Omron Sysmac Studio project CIF105与4543V通讯 (Sysmac Studio 1.25.1.0, StandardProject)

# Controller new_Controller_0: NX1P2-9024DT version 1.16
Task PrimaryTask (priority 4, period or condition 2000): Program0

TYPE TypeBD4543 : STRUCT
    PV : ARRAY[0..15] OF INT;  (* 实际温度、报警状态、故障状态（只读） *)
    RUNF : INT;  (* 通道故障（只读） *)
    ALF1 : INT;  (* 报警1状态（只读） *)
    ALF2 : INT;  (* 报警2状态（只读） *)
    ONB : INT;  (* 启动温控（可读可写） *)
    ATUB : INT;  (* 自整定（可读可写） *)
    SV : ARRAY[0..15] OF INT;  (* 设定温度（可读可写） *)
    Pb : ARRAY[0..15] OF INT;  (* 温度偏置（可读可写） *)
    running : INT;  (* 通信计数 *)
    error : INT;  (* 通信故障计数 *)
    tmp : ARRAY[0..34] OF INT;  (* 中间数据（只读） *)
END_STRUCT END_TYPE

VAR_GLOBAL
    P1 : _sDEVICE_PORT;
    P0 : _sDEVICE_PORT;
END_VAR
VAR_GLOBAL CONSTANT
    Port1 : _sNXUNIT_ID := (NodeAdr := 65535, IPAdr := [5(16#FF)], UnitNo := 1, Path := [16#1, 16#0, 16#2, 16#0, 16#1, 59(16#0)], PathLength := 6);
END_VAR
VAR_GLOBAL
    BD4543 : ARRAY[0..9] OF TypeBD4543;  (* published *)
END_VAR
VAR_GLOBAL CONSTANT
    Port0 : _sOPTBOARD_ID := (SlotNo := 1, IPAdr := [5(16#0)]);
END_VAR

PROGRAM Program0
VAR
    abc : BOOL;
    CMM : BD_Modbus;
END_VAR
VAR_EXTERNAL
    P1 : _sDEVICE_PORT;
END_VAR
VAR_EXTERNAL CONSTANT
    Port1 : _sNXUNIT_ID;
END_VAR
VAR_EXTERNAL
    P0 : _sDEVICE_PORT;
END_VAR
VAR_EXTERNAL CONSTANT
    Port0 : _sOPTBOARD_ID;
END_VAR

(* Section Section0: ladder, written here as Structured Text *)

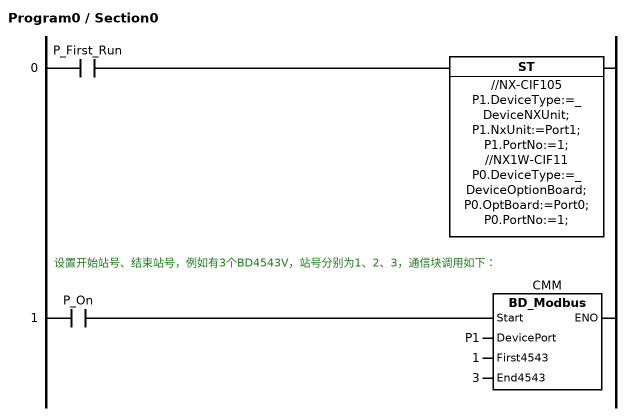
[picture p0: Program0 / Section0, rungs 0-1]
(* Rung 0 *)
IF P_First_Run THEN
    //NX-CIF105
    P1.DeviceType:=_DeviceNXUnit;
    P1.NxUnit:=Port1;
    P1.PortNo:=1;
    
    //NX1W-CIF11
    P0.DeviceType:=_DeviceOptionBoard;
    P0.OptBoard:=Port0;
    P0.PortNo:=1;
END_IF;
(* Rung 1: 设置开始站号、结束站号，例如有3个BD4543V，站号分别为1、2、3，通信块调用如下： *)
CMM(Start := P_On, DevicePort := P1, First4543 := 1, End4543 := 3);
END_PROGRAM

FUNCTION_BLOCK BD_Modbus
VAR
    StartRead : BOOL;
    CurrentSlave : UINT;
    ReadCmd : _sSERIAL_MODBUSRTU_READ;
    Option : _sSERIAL_MODBUSRTU_OPTION;
    Busy1 : BOOL;
    Done1 : BOOL;
    Error1 : BOOL;
    MB_READ_REG : NX_ModbusRtuRead;
    StartWrite : BOOL;
    MB_WRITE_REG : NX_ModbusRtuWrite;
    Done2 : BOOL;
    Busy2 : BOOL;
    Error2 : BOOL;
    WriteCmd : _sSERIAL_MODBUSRTU_WRITE;
    State : INT;
    Index : INT;
    i : INT;
    j : INT;
    k : INT;
    timer1 : TIME;
    OverTime : BOOL;
    Time1 : TON;
    BUSY : BOOL := False;
    errorID : WORD;
    erorIDEX : DWORD;
    ReadSize : UINT;
    recvbuff : ARRAY[0..120] OF WORD;
    senbuff : ARRAY[0..120] OF WORD;
END_VAR
VAR_INPUT
    Start : BOOL;
    DevicePort : _sDEVICE_PORT;
    First4543 : UINT;  (* 首个4543站号 *)
    End4543 : UINT;  (* 末个4543站号 *)
END_VAR
VAR_EXTERNAL
    BD4543 : ARRAY[0..9] OF TypeBD4543;
END_VAR
(* ladder, written here as Structured Text *)

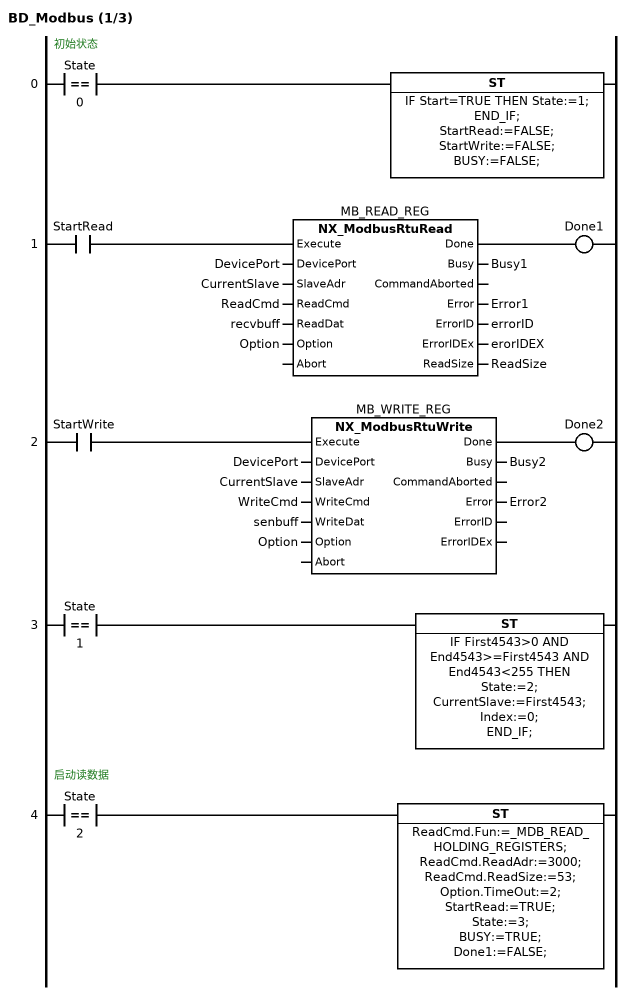
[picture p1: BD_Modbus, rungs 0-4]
(* Rung 0: 初始状态 *)
IF State = 0 THEN
    IF Start=TRUE THEN State:=1; 
    END_IF;
    StartRead:=FALSE;
    StartWrite:=FALSE;
    BUSY:=FALSE;
END_IF;
(* Rung 1 *)
MB_READ_REG(Execute := StartRead, DevicePort := DevicePort, SlaveAdr := CurrentSlave, ReadCmd := ReadCmd, ReadDat := recvbuff, Option := Option, Busy => Busy1, Error => Error1, ErrorID => errorID, ErrorIDEx => erorIDEX, ReadSize => ReadSize);
Done1 := MB_READ_REG.Done;
(* Rung 2 *)
MB_WRITE_REG(Execute := StartWrite, DevicePort := DevicePort, SlaveAdr := CurrentSlave, WriteCmd := WriteCmd, WriteDat := senbuff, Option := Option, Busy => Busy2, Error => Error2);
Done2 := MB_WRITE_REG.Done;
(* Rung 3 *)
IF State = 1 THEN
    IF First4543>0 AND End4543>=First4543 AND End4543<255 THEN
    	State:=2;
    	CurrentSlave:=First4543;
    	Index:=0;
    END_IF;
END_IF;
(* Rung 4: 启动读数据 *)
IF State = 2 THEN
    ReadCmd.Fun:=_MDB_READ_HOLDING_REGISTERS;
    ReadCmd.ReadAdr:=3000;
    ReadCmd.ReadSize:=53;
    Option.TimeOut:=2;
    StartRead:=TRUE;
    State:=3;
    BUSY:=TRUE;
    Done1:=FALSE;
END_IF;

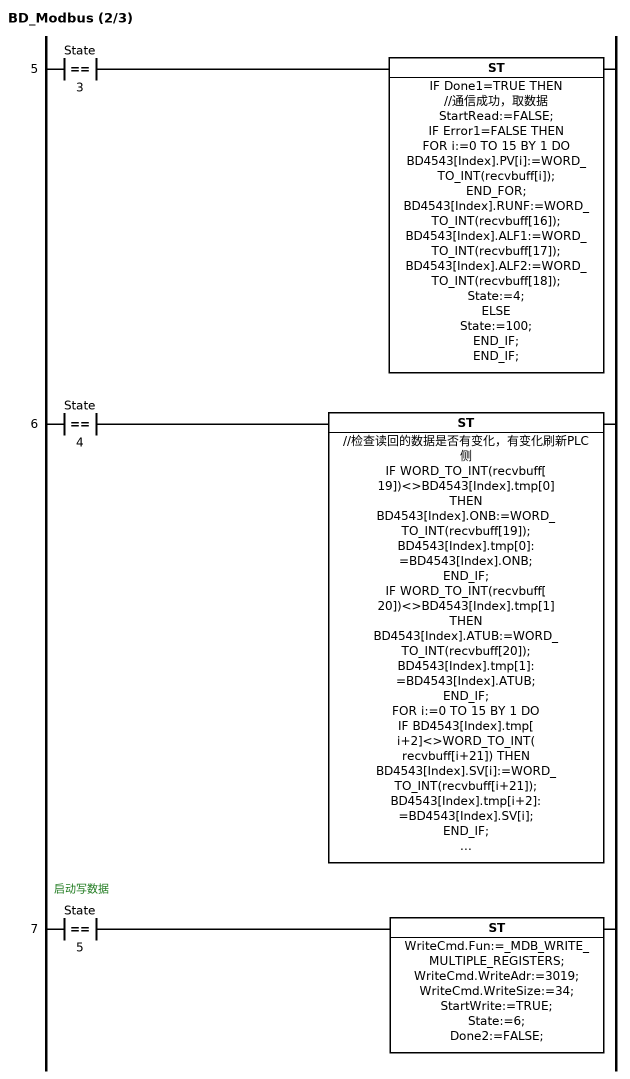
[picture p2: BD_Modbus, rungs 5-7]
(* Rung 5 *)
IF State = 3 THEN
    IF Done1=TRUE THEN			//通信成功，取数据
    	StartRead:=FALSE;
    	IF Error1=FALSE THEN	
    		FOR i:=0 TO 15 BY 1 DO
    			BD4543[Index].PV[i]:=WORD_TO_INT(recvbuff[i]);
    		END_FOR;		
    		BD4543[Index].RUNF:=WORD_TO_INT(recvbuff[16]);
    		BD4543[Index].ALF1:=WORD_TO_INT(recvbuff[17]);
    		BD4543[Index].ALF2:=WORD_TO_INT(recvbuff[18]);
    		State:=4;
    	ELSE
    		State:=100;
    	END_IF;
    END_IF;
END_IF;
(* Rung 6 *)
IF State = 4 THEN
    //检查读回的数据是否有变化，有变化刷新PLC侧
    IF WORD_TO_INT(recvbuff[19])<>BD4543[Index].tmp[0] THEN
    	BD4543[Index].ONB:=WORD_TO_INT(recvbuff[19]);
    	BD4543[Index].tmp[0]:=BD4543[Index].ONB;
    END_IF;
    IF WORD_TO_INT(recvbuff[20])<>BD4543[Index].tmp[1] THEN
    	BD4543[Index].ATUB:=WORD_TO_INT(recvbuff[20]);
    	BD4543[Index].tmp[1]:=BD4543[Index].ATUB;
    END_IF;
    FOR i:=0 TO 15 BY 1 DO
    	IF BD4543[Index].tmp[i+2]<>WORD_TO_INT(recvbuff[i+21]) THEN
    		BD4543[Index].SV[i]:=WORD_TO_INT(recvbuff[i+21]);
    		BD4543[Index].tmp[i+2]:=BD4543[Index].SV[i];
    	END_IF;
    	IF BD4543[Index].tmp[i+18]<>WORD_TO_INT(recvbuff[i+37]) THEN
    		BD4543[Index].Pb[i]:=WORD_TO_INT(recvbuff[i+37]);
    		BD4543[Index].tmp[i+18]:=BD4543[Index].Pb[i];
    	END_IF;
    END_FOR;
    
    k:=0;		//检查PLC侧数据是否有变化，有变化则准备写通信
    IF (BD4543[Index].ONB<>BD4543[Index].tmp[0]) OR (BD4543[Index].ATUB<>BD4543[Index].tmp[1])  THEN
        k:=k+1;
    END_IF;
    FOR i:=0 TO 15 BY 1 DO
    	j:=i+2;
    	IF BD4543[Index].tmp[j]<>BD4543[Index].SV[i] THEN
    		k:=k+1;
    	END_IF;
    	j:=i+18;
    	IF BD4543[Index].tmp[j]<>BD4543[Index].Pb[i] THEN
    		k:=k+1;
    	END_IF;
    END_FOR;
    IF k<>0 THEN	//准备要写的数据
    	senbuff[0]:=INT_TO_WORD(BD4543[Index].ONB);
    	senbuff[1]:=INT_TO_WORD(BD4543[Index].ATUB);
    	FOR i:=0 TO 15 BY 1 DO 
    		j:=i+2;
    		senbuff[j]:=INT_TO_WORD(BD4543[Index].SV[i]);
    		j:=i+18;
    		senbuff[j]:=INT_TO_WORD(BD4543[Index].Pb[i]);
    	END_FOR;
    	State:=5;
    ELSE
    	BD4543[Index].running:=BD4543[Index].running+1;
    	BD4543[Index].error:=0;
    	State:=101;
    END_IF;
END_IF;
(* Rung 7: 启动写数据 *)
IF State = 5 THEN
    WriteCmd.Fun:=_MDB_WRITE_MULTIPLE_REGISTERS;
    WriteCmd.WriteAdr:=3019;
    WriteCmd.WriteSize:=34;
    StartWrite:=TRUE;
    State:=6;
    Done2:=FALSE;
END_IF;

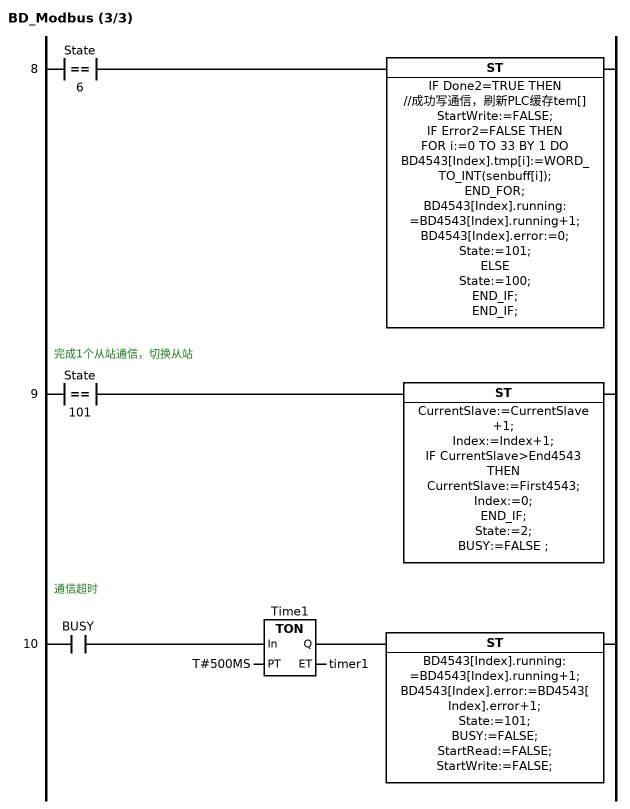
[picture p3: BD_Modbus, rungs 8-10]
(* Rung 8 *)
IF State = 6 THEN
    IF Done2=TRUE THEN		//成功写通信，刷新PLC缓存tem[]
    	StartWrite:=FALSE;
    	IF Error2=FALSE THEN
    		FOR i:=0 TO 33 BY 1 DO
    			BD4543[Index].tmp[i]:=WORD_TO_INT(senbuff[i]);
    		END_FOR;
    		BD4543[Index].running:=BD4543[Index].running+1;
    		BD4543[Index].error:=0;
    		State:=101;
    	ELSE
    		State:=100;
    	END_IF;
    END_IF;
END_IF;
(* Rung 9: 完成1个从站通信，切换从站 *)
IF State = 101 THEN
    CurrentSlave:=CurrentSlave +1;
    Index:=Index+1;
    IF CurrentSlave>End4543 THEN
    	CurrentSlave:=First4543;
    	Index:=0;
    END_IF;
    State:=2;
    BUSY:=FALSE ;
END_IF;
(* Rung 10: 通信超时 *)
Time1(In := BUSY, PT := T#500MS, ET => timer1);
IF Time1.Q THEN
    BD4543[Index].running:=BD4543[Index].running+1;
    BD4543[Index].error:=BD4543[Index].error+1;
    State:=101;
    BUSY:=FALSE;
    StartRead:=FALSE;
    StartWrite:=FALSE;
END_IF;
END_FUNCTION_BLOCK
